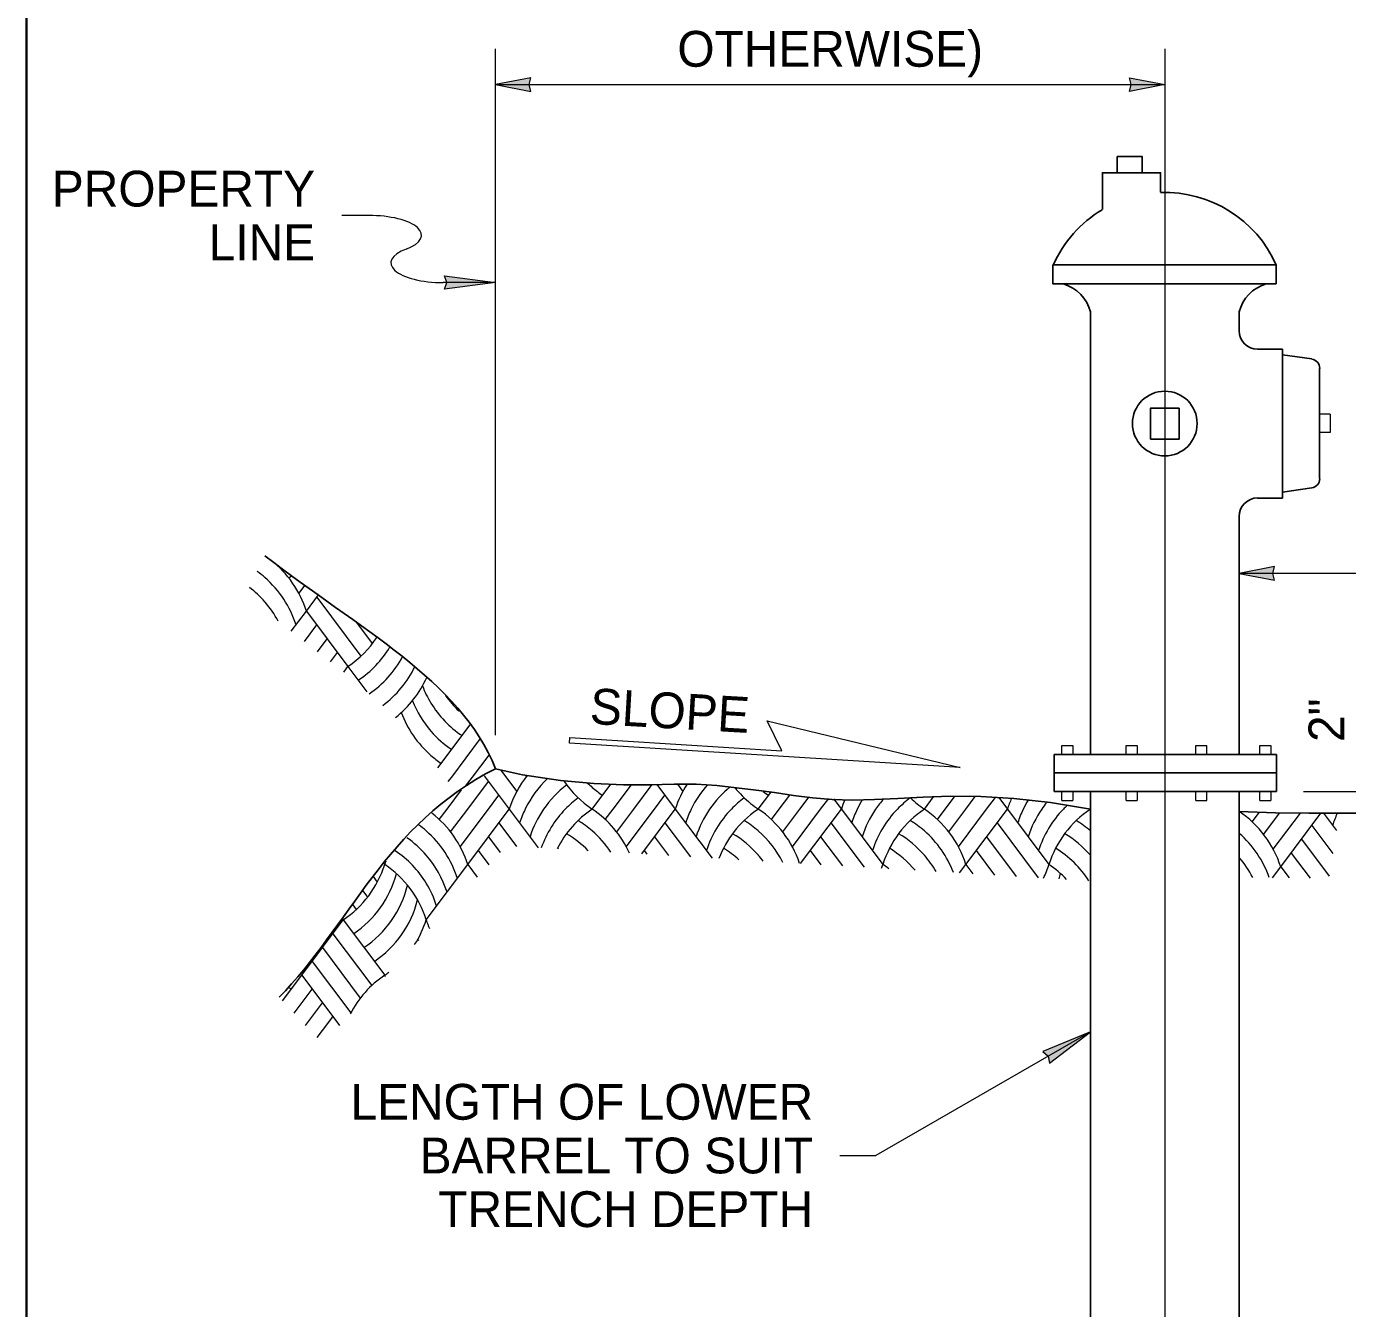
# Model space of a CAD drawing. Extents: x 99860 to 103153, y 99998 to 102077.
# Drawn here: x 99862 to 100453, y 100571 to 101144 of the extents above; entities that cross this region are included whole.
import ezdxf
from ezdxf.enums import TextEntityAlignment as Align

# ---------------------------------------------------------------- set-up
doc = ezdxf.new("R2010")
doc.units = 0
doc.header["$LTSCALE"] = 6.4
for name, color, linetype, lineweight in [('1', 7, 'Continuous', 25), ('14', 7, 'Continuous', 13), ('15', 7, 'Continuous', 13), ('18', 7, 'Continuous', 13), ('20', 7, 'Continuous', 13), ('28', 7, 'Continuous', 13), ('3', 7, 'Continuous', 13), ('6', 7, 'Continuous', 25), ('8', 7, 'Continuous', 25)]:
    doc.layers.add(name, color=color, linetype=linetype, lineweight=lineweight)

msp = doc.modelspace()

# ---------------------------------------------------------------- hatches: boundary and pattern name
at = {"layer": '14'}
msp.add_hatch(color=256, dxfattribs=at).paths.add_polyline_path([(100071.795, 101029.874), (100048.966, 101026.889), (100050.022, 101029.874), (100048.965, 101032.859)])
at = {"layer": '15'}
for points in [[(100071.795, 101118.385), (100087.52, 101115.301), (100086.792, 101118.385), (100087.52, 101121.469)], [(100371.007, 101118.385), (100355.282, 101115.301), (100356.01, 101118.385), (100355.282, 101121.469)], [(100404.282, 100899.872), (100420.007, 100896.788), (100419.279, 100899.872), (100420.007, 100902.956)], [(100337.753, 100694.862), (100316.49, 100686.032), (100318.897, 100683.975), (100319.475, 100680.862)]]:
    msp.add_hatch(color=256, dxfattribs=at).paths.add_polyline_path(points)

# ---------------------------------------------------------------- linework, layer by layer
at = {"layer": '1', "lineweight": 35}
msp.add_lwpolyline([(99862, 99999.5), (103151, 99999.5), (103151, 102075.5), (99862, 102075.5)], close=True, dxfattribs=at)
at = {"layer": '14'}
for p, q in [((100015.06, 101059.874), (100003.06, 101059.874)), ((100071.795, 101029.874), (100048.364, 101029.874))]:
    msp.add_line(p, q, dxfattribs=at)
msp.add_lwpolyline([(100071.795, 101029.874), (100048.966, 101026.889), (100050.022, 101029.874), (100048.965, 101032.859)], close=True, dxfattribs=at)
for centre, start_param, end_param in [((100015.227, 101051.087), 5.4977468, 7.8611267), ((100048.364, 101038.661), 2.3562263, 4.712389)]:
    msp.add_ellipse(centre, major_axis=(23.431, 0), ratio=0.375, start_param=start_param, end_param=end_param, dxfattribs=at)
at = {"layer": '15'}
for p, q in [((100071.795, 100827.522), (100071.795, 101134.385)), ((100371.007, 101134.385), (100371.007, 100280.712)), ((100071.795, 101118.385), (100371.007, 101118.385)), ((100667.807, 100899.872), (100404.282, 100899.872)), ((100433.01, 100802.397), (100473.282, 100802.397)), ((100337.753, 100694.862), (100241.769, 100639.591)), ((100225.769, 100639.591), (100241.769, 100639.591))]:
    msp.add_line(p, q, dxfattribs=at)
for points in [[(100071.795, 101118.385), (100087.52, 101115.301), (100086.792, 101118.385), (100087.52, 101121.469)], [(100371.007, 101118.385), (100355.282, 101115.301), (100356.01, 101118.385), (100355.282, 101121.469)], [(100404.282, 100899.872), (100420.007, 100896.788), (100419.279, 100899.872), (100420.007, 100902.956)], [(100337.753, 100694.862), (100316.49, 100686.032), (100318.897, 100683.975), (100319.475, 100680.862)]]:
    msp.add_lwpolyline(points, close=True, dxfattribs=at)
at = {"layer": '18', "lineweight": 25}
for p, q in [((100337.757, 100818.897), (100337.757, 101016.772)), ((100404.282, 101008.547), (100404.282, 101016.772)), ((100412.482, 101000.035), (100423.707, 101000.035)), ((100423.707, 101000.035), (100423.707, 100933.522)), ((100423.707, 100997.622), (100436.72, 100995.772)), ((100440.145, 100991.522), (100440.145, 100942.31)), ((100423.707, 100936.197), (100436.72, 100938.047)), ((100412.482, 100933.522), (100423.707, 100933.522)), ((100404.282, 100818.897), (100404.282, 100925.285)), ((100421.02, 100818.897), (100321.545, 100818.897)), ((100321.545, 100802.397), (100321.545, 100818.897)), ((100421.02, 100802.397), (100421.02, 100818.897)), ((100421.02, 100810.672), (100321.545, 100810.672)), ((100321.545, 100802.397), (100421.02, 100802.397))]:
    msp.add_line(p, q, dxfattribs=at)
at = {"layer": '18'}
for p, q in [((100444.982, 100971.047), (100440.145, 100971.047)), ((100444.982, 100971.047), (100444.982, 100962.81)), ((100444.982, 100962.81), (100440.145, 100962.81)), ((100324.907, 100822.972), (100329.87, 100822.972)), ((100324.907, 100818.897), (100324.907, 100822.972)), ((100329.87, 100822.972), (100329.87, 100818.897)), ((100353.707, 100822.935), (100358.67, 100822.935)), ((100353.707, 100818.897), (100353.707, 100822.935)), ((100358.67, 100822.935), (100358.67, 100818.897)), ((100384.882, 100822.972), (100389.845, 100822.972)), ((100384.882, 100818.897), (100384.882, 100822.972)), ((100389.845, 100818.897), (100389.845, 100822.972)), ((100413.47, 100822.91), (100418.395, 100822.91)), ((100413.47, 100818.897), (100413.47, 100822.91)), ((100418.395, 100822.91), (100418.395, 100818.835)), ((100324.907, 100798.297), (100324.907, 100802.397)), ((100329.87, 100802.397), (100329.87, 100798.297)), ((100353.707, 100798.297), (100353.707, 100802.397)), ((100358.67, 100802.397), (100358.67, 100798.297)), ((100384.882, 100798.335), (100384.882, 100802.397)), ((100389.845, 100798.335), (100389.845, 100802.397)), ((100413.47, 100798.272), (100413.47, 100802.397)), ((100418.395, 100802.397), (100418.395, 100798.272)), ((100324.907, 100798.297), (100329.87, 100798.297)), ((100353.707, 100798.297), (100358.67, 100798.297)), ((100384.882, 100798.335), (100389.845, 100798.335)), ((100413.47, 100798.272), (100418.395, 100798.272))]:
    msp.add_line(p, q, dxfattribs=at)
at = {"layer": '18', "lineweight": 25}
for points in [[(100349.732, 101079.01), (100349.732, 101086.222), (100360.92, 101086.222), (100360.92, 101079.01)], [(100369.157, 101070.247), (100369.157, 101079.01), (100343.095, 101079.01), (100343.095, 101062.535)]]:
    msp.add_lwpolyline(points, dxfattribs=at)
for points in [[(100420.745, 101029.26), (100420.745, 101037.772), (100320.982, 101037.772), (100320.982, 101029.26)], [(100364.62, 100959.847), (100364.62, 100973.697), (100377.382, 100973.697), (100377.382, 100959.847)]]:
    msp.add_lwpolyline(points, close=True, dxfattribs=at)
msp.add_circle((100371.012, 100966.855), 14.468, dxfattribs=at)
for centre, radius, start, end in [((100371.012, 101015.624), 54.543, 23.89556, 91.97586), ((100371.012, 101015.624), 54.543, 120.92859, 156.10444), ((100320.83, 101012.49), 17.465, 14.112, 73.77865), ((100421.195, 101012.49), 17.465, 106.22135, 165.888), ((100412.569, 101008.411), 8.311, 180, 270), ((100436.109, 100991.532), 4.156, 0, 81.50484), ((100436.109, 100942.177), 4.156, 278.49516, 0), ((100412.569, 100925.298), 8.311, 90, 180)]:
    msp.add_arc(centre, radius, start, end, dxfattribs=at)
at = {"layer": '28'}
for p, q in [((99974.437, 100903.117), (99974.621, 100903.363)), ((99979.534, 100897.538), (99980.623, 100898.99)), ((99983.838, 100890.903), (99986.624, 100894.618)), ((99987.181, 100882.986), (99992.626, 100890.246)), ((99991.821, 100889.173), (100011.56, 100862.855)), ((99980.409, 100873.957), (99987.181, 100882.986)), ((99987.181, 100882.986), (100005.742, 100858.237)), ((99986.275, 100869.404), (99991.821, 100876.799)), ((100009.539, 100877.924), (100016.657, 100868.434)), ((99992.141, 100864.851), (99996.462, 100870.612)), ((99998.007, 100860.298), (100001.102, 100864.424)), ((100003.874, 100855.745), (100005.742, 100858.237)), ((100005.742, 100858.237), (100014.196, 100846.965)), ((100050.512, 100843.685), (100050.696, 100843.93)), ((100046.007, 100812.93), (100060.371, 100832.082)), ((100052.145, 100808.74), (100065.081, 100825.988)), ((100061.426, 100808.74), (100068.844, 100818.631)), ((100073.991, 100812.034), (100081.243, 100802.364)), ((100050.647, 100806.743), (100052.145, 100808.74)), ((100058.369, 100804.664), (100061.426, 100808.74)), ((100059.338, 100794.447), (100068.619, 100806.822)), ((100066.708, 100809.37), (100077.9, 100794.447)), ((100085.052, 100809.66), (100085.547, 100809)), ((100115.022, 100794.447), (100123.365, 100805.571)), ((100124.303, 100794.447), (100132.487, 100805.36)), ((100133.583, 100794.447), (100141.845, 100805.463)), ((100143.86, 100805.493), (100152.145, 100794.447)), ((100153.054, 100805.61), (100155.488, 100802.364)), ((100050.058, 100794.447), (100056.511, 100803.052)), ((100068.619, 100794.447), (100073.26, 100800.634)), ((100142.864, 100794.447), (100147.505, 100800.634)), ((100189.267, 100794.447), (100194.866, 100801.912)), ((100198.548, 100794.447), (100203.284, 100800.763)), ((100207.828, 100794.447), (100211.966, 100799.964)), ((100217.109, 100794.447), (100220.717, 100799.258)), ((100222.915, 100799.08), (100226.39, 100794.447)), ((100263.512, 100794.447), (100267.633, 100799.942)), ((100272.793, 100794.447), (100276.972, 100800.02)), ((100282.073, 100794.447), (100286.262, 100800.031)), ((100291.354, 100794.447), (100295.276, 100799.677)), ((100296.775, 100799.594), (100300.635, 100794.447)), ((100046.595, 100789.83), (100050.058, 100794.447)), ((100051.691, 100784.251), (100059.338, 100794.447)), ((100055.995, 100777.615), (100068.619, 100794.447)), ((100059.338, 100769.698), (100077.9, 100794.447)), ((100077.9, 100794.447), (100090.848, 100777.183)), ((100120.84, 100789.83), (100124.303, 100794.447)), ((100125.936, 100784.251), (100133.583, 100794.447)), ((100130.24, 100777.615), (100142.864, 100794.447)), ((100137.119, 100774.413), (100152.145, 100794.447)), ((100152.145, 100794.447), (100168.584, 100772.529)), ((100195.085, 100789.83), (100198.548, 100794.447)), ((100200.181, 100784.251), (100207.828, 100794.447)), ((100204.485, 100777.615), (100217.109, 100794.447)), ((100208.173, 100770.159), (100226.39, 100794.447)), ((100226.39, 100794.447), (100244.951, 100769.698)), ((100269.33, 100789.83), (100272.793, 100794.447)), ((100274.426, 100784.251), (100282.073, 100794.447)), ((100278.73, 100777.615), (100291.354, 100794.447)), ((100282.073, 100769.698), (100300.635, 100794.447)), ((100300.635, 100794.447), (100319.196, 100769.698)), ((100410.1, 100788.755), (100413.343, 100793.079)), ((100415.196, 100783.176), (100422.433, 100792.825)), ((100419.5, 100776.54), (100431.634, 100792.719)), ((100422.843, 100768.623), (100440.835, 100792.613)), ((100441.984, 100792.599), (100447.752, 100784.909)), ((100073.26, 100788.26), (100081.131, 100777.765)), ((100147.505, 100788.26), (100158.867, 100773.111)), ((100221.75, 100788.26), (100236.602, 100768.456)), ((100295.995, 100788.26), (100314.338, 100763.802)), ((100436.765, 100787.185), (100446.147, 100774.675)), ((100068.619, 100782.073), (100073.896, 100775.037)), ((100142.864, 100782.073), (100149.149, 100773.692)), ((100217.109, 100782.073), (100226.885, 100769.038)), ((100291.354, 100782.073), (100304.621, 100764.384)), ((100432.124, 100780.998), (100444.542, 100764.44)), ((100063.979, 100775.886), (100068.757, 100769.515)), ((100138.224, 100775.886), (100139.432, 100774.274)), ((100212.469, 100775.886), (100217.168, 100769.62)), ((100286.714, 100775.886), (100294.904, 100764.966)), ((100427.484, 100774.811), (100435.954, 100763.517)), ((100021.856, 100770.179), (100022.216, 100769.698)), ((100040.777, 100744.95), (100059.338, 100769.698)), ((100059.338, 100769.698), (100063.617, 100763.993)), ((100279.228, 100765.904), (100282.073, 100769.698)), ((100282.073, 100769.698), (100285.187, 100765.548)), ((100016.981, 100764.304), (100018.873, 100761.781)), ((100419.223, 100763.796), (100422.843, 100768.623)), ((100422.843, 100768.623), (100426.556, 100763.674)), ((100012.435, 100757.992), (100014.569, 100755.146)), ((100007.888, 100751.68), (100009.473, 100749.567)), ((100003.341, 100745.368), (100003.655, 100744.95)), ((99985.093, 100720.201), (100003.655, 100744.95)), ((100003.655, 100744.95), (100022.216, 100720.201)), ((99999.015, 100738.763), (100016.399, 100715.584)), ((99994.374, 100732.575), (100011.302, 100710.005)), ((99989.734, 100726.388), (100006.998, 100703.369)), ((99976.472, 100708.706), (99985.093, 100720.201)), ((99985.093, 100720.201), (100001.944, 100697.733)), ((99981.646, 100703.231), (99989.734, 100714.014)), ((99986.821, 100697.755), (99994.374, 100707.827)), ((99994.374, 100695.452), (99999.015, 100701.639)), ((99991.995, 100692.28), (99994.374, 100695.452))]:
    msp.add_line(p, q, dxfattribs=at)
for centre, start, end in [((99994.821, 100868.749), 123.90404, 123.90495), ((99942.419, 100868.749), 56.08421, 56.09573), ((99942.419, 100868.749), 17.6434, 51.76701), ((99937.779, 100862.562), 48.95968, 54.26438), ((99933.139, 100856.375), 40.94134, 52.42136), ((99937.778, 100862.562), 17.6434, 48.95974), ((99933.138, 100856.375), 28.06951, 40.94141), ((99979.542, 100897.223), 303.90361, 326.44558), ((99984.182, 100891.036), 303.90361, 329.21926), ((99988.822, 100884.848), 304.27416, 331.76659), ((99993.463, 100878.661), 306.34246, 334.24493), ((99998.103, 100872.474), 308.01718, 336.01166), ((100082.987, 100866.287), 200.87781, 211.33197), ((100078.347, 100860.1), 201.43438, 220.94161), ((100082.986, 100866.287), 211.33188, 236.09639), ((100087.627, 100872.474), 215.44432, 226.55916), ((100073.707, 100853.912), 200.24322, 228.95992), ((100078.346, 100860.1), 220.94154, 236.09639), ((100073.705, 100853.912), 228.95986, 236.09639), ((100122.662, 100780.21), 141.39378, 162.3566), ((100127.303, 100774.023), 133.46987, 154.22661), ((100131.943, 100767.836), 127.1006, 145.49109), ((100141.224, 100833.433), 214.14534, 236.09639), ((100145.864, 100839.62), 225.51765, 228.95992), ((100196.907, 100780.21), 147.26638, 162.3566), ((100201.548, 100774.023), 138.21479, 154.2266), ((100206.188, 100767.836), 128.96048, 145.4911), ((100136.583, 100761.649), 126.331, 135.71278), ((100145.863, 100839.62), 228.95986, 236.09639), ((100210.828, 100761.649), 126.331, 135.71278), ((100215.469, 100833.433), 218.64568, 230.83364), ((100220.108, 100839.62), 232.46241, 236.09639), ((100271.152, 100780.21), 156.85489, 162.3566), ((100275.793, 100774.023), 148.48666, 154.22661), ((100280.433, 100767.836), 138.49583, 145.49109), ((100285.073, 100761.649), 126.36274, 135.71278), ((100289.714, 100833.433), 226.29606, 236.09639), ((100345.397, 100780.21), 156.05062, 162.3566), ((100350.038, 100774.023), 148.61433, 154.22661), ((100014.576, 100755.462), 17.6434, 52.22548), ((100127.303, 100774.023), 154.22654, 162.3566), ((100131.943, 100767.836), 145.49102, 162.3566), ((100136.583, 100761.649), 135.71269, 160.79455), ((100141.224, 100755.462), 123.90361, 153.15099), ((100088.821, 100755.462), 24.23123, 56.09634), ((100201.548, 100774.023), 154.22654, 162.3566), ((100206.188, 100767.836), 145.49102, 162.3566), ((100210.828, 100761.649), 135.71269, 162.3566), ((100215.469, 100755.462), 124.95971, 158.93313), ((100215.469, 100833.433), 230.83364, 236.09639), ((100215.469, 100755.462), 123.90361, 124.95971), ((100163.066, 100755.462), 18.27197, 56.09634), ((100275.793, 100774.023), 154.22654, 162.3566), ((100280.433, 100767.836), 145.49102, 162.3566), ((100285.073, 100761.649), 135.71269, 162.3566), ((100289.714, 100755.462), 123.90361, 162.3566), ((100237.311, 100755.462), 17.6434, 56.09634), ((100350.038, 100774.023), 154.22654, 162.3566), ((100354.678, 100767.836), 145.49102, 162.3566), ((100359.318, 100761.649), 135.71269, 162.3566), ((100354.678, 100767.836), 141.09014, 145.49109), ((100363.959, 100755.462), 123.9045, 162.3566), ((100359.318, 100761.649), 133.01819, 135.71278), ((100363.959, 100755.462), 123.90361, 123.9045), ((100378.081, 100754.387), 56.09552, 56.09634), ((100378.081, 100754.387), 17.6434, 56.09552), ((100430.484, 100754.387), 123.90361, 123.90451), ((100490.808, 100772.948), 155.27178, 162.3566), ((100009.937, 100749.275), 48.95968, 54.40953), ((100084.182, 100749.275), 48.95968, 58.54646), ((100158.427, 100749.275), 48.95968, 58.54646), ((100232.672, 100749.275), 48.95968, 58.54646), ((100306.917, 100749.275), 48.96078, 58.54646), ((100005.297, 100743.087), 40.94134, 55.21207), ((100009.936, 100749.275), 17.6434, 48.95974), ((100079.542, 100743.087), 44.21699, 59.30215), ((100084.181, 100749.275), 33.55654, 48.95974), ((100153.787, 100743.087), 40.94134, 59.30215), ((100158.426, 100749.275), 27.04515, 48.95974), ((100228.032, 100743.087), 40.94134, 59.30215), ((100232.671, 100749.275), 20.94461, 48.95974), ((100302.277, 100743.087), 40.9426, 59.30215), ((100373.441, 100748.2), 19.42479, 48.95974), ((100000.656, 100736.9), 31.33163, 56.01598), ((100074.901, 100736.9), 57.77943, 58.48736), ((100149.146, 100736.9), 48.00745, 58.48736), ((100223.391, 100736.9), 39.99999, 58.48736), ((100297.636, 100736.9), 32.94061, 58.48736), ((99977.454, 100783.935), 303.90361, 342.3566), ((100066.979, 100755.462), 160.53199, 162.3566), ((99996.016, 100730.713), 17.6434, 56.09639), ((100005.295, 100743.087), 17.6434, 40.94141), ((100153.785, 100743.087), 36.70183, 40.94141), ((100200.189, 100783.935), 340.15732, 342.3566), ((100218.751, 100730.713), 52.14305, 56.09639), ((100228.03, 100743.087), 29.94292, 40.94141), ((100274.434, 100783.935), 334.42061, 342.3566), ((100292.996, 100730.713), 43.48895, 56.09639), ((100368.8, 100742.012), 27.83434, 40.94141), ((99982.095, 100777.748), 303.90361, 345.01126), ((100279.075, 100777.748), 342.00735, 345.01126), ((99986.735, 100771.561), 303.90361, 346.31988), ((100000.655, 100736.9), 17.6434, 31.33172), ((99991.375, 100765.374), 303.90361, 345.77133), ((99996.016, 100759.186), 327.39306, 342.3566), ((100085.539, 100759.186), 197.64354, 202.76467), ((100080.9, 100752.999), 200.87781, 201.66301), ((100011.294, 100759.186), 236.03653, 236.09639), ((100048.417, 100681.215), 123.90361, 152.51833), ((99996.016, 100759.186), 303.90361, 306.71404), ((100066.979, 100734.438), 197.6434, 198.29794), ((100006.654, 100752.999), 234.84855, 236.09639)]:
    msp.add_arc(centre, 46.972, start, end, dxfattribs=at)
at = {"layer": '3'}
msp.add_lwpolyline([(100105.029, 100826.45), (100199.823, 100820.534), (100193.166, 100833.934), (100279.535, 100813.079), (100104.875, 100823.981)], close=True, dxfattribs=at)
at = {"layer": '6'}
for p, q in [((100337.757, 100510.872), (100337.757, 100802.397)), ((100404.282, 100510.872), (100404.282, 100802.397))]:
    msp.add_line(p, q, dxfattribs=at)
at = {"layer": '8'}
for points in [[(100337.757, 100794.447), (100319.945, 100797.347), (100303.47, 100799.222), (100288.82, 100800.035), (100275.257, 100800.272), (100263.045, 100799.747), (100251.607, 100799.222), (100241.22, 100798.697), (100231.382, 100798.397), (100222.345, 100798.697), (100213.557, 100799.472), (100205.045, 100800.522), (100196.532, 100801.885), (100188.295, 100802.96), (100179.507, 100804.01), (100170.757, 100805.085), (100161.407, 100805.61), (100151.607, 100805.61), (100140.97, 100805.36), (100129.007, 100805.36), (100115.682, 100805.86), (100100.782, 100807.21), (100083.77, 100809.86), (100071.795, 100812.522)], [(100461.72, 100792.597), (100448.957, 100792.597), (100435.395, 100792.597), (100420.495, 100792.847), (100404.282, 100793.372)]]:
    msp.add_lwpolyline(points, dxfattribs=at)
for points in [[(100071.795, 100812.522), (100055.857, 100852.422), (100010.657, 100874.997), (99968.62, 100907.735)], [(100071.795, 100812.522), (100022.645, 100788.06), (100005.932, 100741.372), (99974.945, 100710.322)]]:
    msp.add_open_spline(points, degree=3, dxfattribs=at)

# ---------------------------------------------------------------- texts
at = {"layer": '20'}
msp.add_text('OTHERWISE)', height=16, dxfattribs=at).set_placement((100221.405, 101126.385), align=Align.CENTER)
for s, p in [('PROPERTY', (99991.067, 101063.874)), ('LINE', (99991.068, 101039.874)), ('LENGTH OF LOWER', (100213.775, 100655.591)), ('BARREL TO SUIT', (100213.775, 100631.591)), ('TRENCH DEPTH', (100213.775, 100607.591))]:
    msp.add_text(s, height=16, dxfattribs=at).set_placement(p, align=Align.RIGHT)
msp.add_text('SLOPE', height=16, rotation=356.677, dxfattribs=at).set_placement((100149.264, 100830.559), align=Align.CENTER)
msp.add_text('2"', height=16, rotation=90, dxfattribs=at).set_placement((100451.287, 100824.463))

doc.saveas('drawing.dxf')
